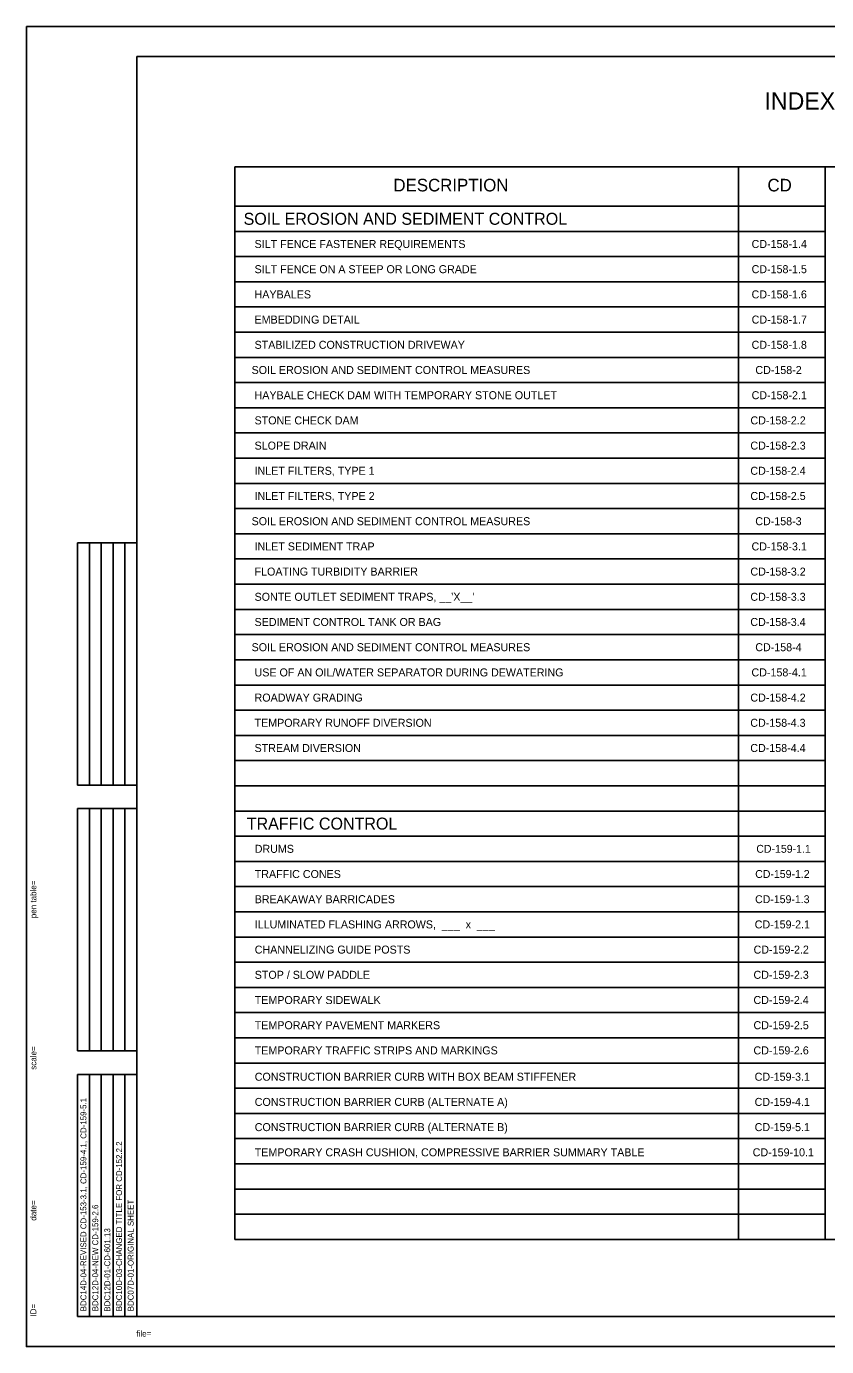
# Model space of a CAD drawing. Extents: x 503613 to 504661, y 498262 to 498922.
# Drawn here: x 503613 to 504013, y 498262 to 498922 of the extents above; entities that cross this region are included whole.
import ezdxf

# ---------------------------------------------------------------- set-up
doc = ezdxf.new("R2010")
doc.units = 0
for name, color, linetype in [('1', 7, 'Continuous'), ('39', 7, 'Continuous'), ('41', 7, 'Continuous')]:
    doc.layers.add(name, color=color, linetype=linetype)

msp = doc.modelspace()

# ---------------------------------------------------------------- linework, layer by layer
at = {"layer": '1'}
for p, q in [((504661.22, 498922.31), (503613.04, 498922.31)), ((504658.22, 498907.31), (503668.22, 498907.31)), ((503668.22, 498907.31), (503668.22, 498277.31)), ((503717.27, 498852.12), (504603.1, 498852.12)), ((503717.27, 498315.9), (503717.27, 498852.12)), ((503717.27, 498832.43), (503717.27, 498852.12)), ((503969.24, 498315.9), (503969.24, 498852.12)), ((503969.24, 498832.43), (503969.24, 498852.12)), ((504012.55, 498315.9), (504012.55, 498852.12)), ((504012.55, 498832.43), (504012.55, 498852.12)), ((503717.27, 498832.43), (504012.55, 498832.43)), ((503717.27, 498819.83), (504012.55, 498819.83)), ((503717.27, 498807.24), (504012.55, 498807.24)), ((503717.27, 498794.64), (504012.55, 498794.64)), ((503717.27, 498782.04), (504012.55, 498782.04)), ((503717.27, 498769.44), (504012.55, 498769.44)), ((503717.27, 498756.84), (504012.55, 498756.84)), ((503717.27, 498744.24), (504012.55, 498744.24)), ((503717.27, 498731.65), (504012.55, 498731.65)), ((503717.27, 498719.05), (504012.55, 498719.05)), ((503717.27, 498706.45), (504012.55, 498706.45)), ((503717.27, 498693.85), (504012.55, 498693.85)), ((503717.27, 498681.25), (504012.55, 498681.25)), ((503638.69, 498664.13), (503668.22, 498664.13)), ((503638.69, 498543.06), (503638.69, 498664.13)), ((503644.59, 498543.06), (503644.59, 498664.13)), ((503650.5, 498543.06), (503650.5, 498664.13)), ((503656.41, 498543.06), (503656.41, 498664.13)), ((503662.31, 498543.06), (503662.31, 498664.13)), ((503717.27, 498668.65), (504012.55, 498668.65)), ((503717.27, 498656.06), (504012.55, 498656.06)), ((503717.27, 498643.46), (504012.55, 498643.46)), ((503717.27, 498630.86), (504012.55, 498630.86)), ((503717.27, 498618.26), (504012.55, 498618.26)), ((503717.27, 498605.66), (504012.55, 498605.66)), ((503717.27, 498593.06), (504012.55, 498593.06)), ((503717.27, 498580.46), (504012.55, 498580.46)), ((503717.27, 498567.87), (504012.55, 498567.87)), ((503717.27, 498555.27), (504012.55, 498555.27)), ((503668.22, 498543.06), (503638.69, 498543.06)), ((503717.27, 498542.67), (504012.55, 498542.67)), ((503638.69, 498531.25), (503668.22, 498531.25)), ((503638.69, 498410.19), (503638.69, 498531.25)), ((503644.59, 498410.19), (503644.59, 498531.25)), ((503650.5, 498410.19), (503650.5, 498531.25)), ((503656.41, 498410.19), (503656.41, 498531.25)), ((503662.31, 498410.19), (503662.31, 498531.25)), ((503717.27, 498530.07), (504012.55, 498530.07)), ((503717.27, 498517.47), (504012.55, 498517.47)), ((503717.27, 498504.87), (504012.55, 498504.87)), ((503717.27, 498492.28), (504012.55, 498492.28)), ((503717.27, 498479.68), (504012.55, 498479.68)), ((503717.27, 498467.08), (504012.55, 498467.08)), ((503717.27, 498454.48), (504012.55, 498454.48)), ((503717.27, 498441.88), (504012.55, 498441.88)), ((503717.27, 498429.28), (504012.55, 498429.28)), ((503717.27, 498416.68), (504012.55, 498416.68)), ((503668.22, 498410.19), (503638.69, 498410.19)), ((503717.27, 498404.09), (504012.55, 498404.09)), ((503638.69, 498277.31), (503638.69, 498398.38)), ((503638.69, 498398.38), (503668.22, 498398.38)), ((503644.59, 498277.31), (503644.59, 498398.38)), ((503650.5, 498277.31), (503650.5, 498398.38)), ((503656.41, 498277.31), (503656.41, 498398.38)), ((503662.31, 498277.31), (503662.31, 498398.38)), ((503717.27, 498391.49), (504012.55, 498391.49)), ((503717.27, 498378.89), (504012.55, 498378.89)), ((503717.27, 498366.29), (504012.55, 498366.29)), ((503717.27, 498353.69), (504012.55, 498353.69)), ((503717.27, 498341.09), (504012.55, 498341.09)), ((503717.27, 498328.5), (504012.55, 498328.5)), ((503717.27, 498315.9), (504603.1, 498315.9)), ((503717.27, 498315.9), (504012.55, 498315.9)), ((503668.22, 498277.31), (503638.69, 498277.31)), ((503668.22, 498277.31), (504658.22, 498277.31)), ((504661.22, 498262.31), (503613.04, 498262.31))]:
    msp.add_line(p, q, dxfattribs=at)
at = {"layer": '41'}
msp.add_lwpolyline([(503613.04, 498922.31), (504661.22, 498922.31), (504661.22, 498262.31), (503613.04, 498262.31)], close=True, dxfattribs=at)

# ---------------------------------------------------------------- texts
at = {"layer": '1'}
for s, height, p in [('DESCRIPTION', 6.2992, (503796.64, 498839.82)), ('CD', 6.299, (503983.75, 498839.82))]:
    msp.add_text(s, height=height, dxfattribs=at).set_placement(p)
for s, height, rotation, p in [('...................pentable..................', 0.0432, 90, (503618.04, 498500.38)), ('pen table=', 3, 90, (503618.04, 498476.47)), ('scale=', 3, 90, (503618.04, 498400.71)), ('......scale......', 0.0432, 90, (503618.04, 498415.38)), ('date=', 3, 90, (503618.04, 498325.25)), ('.......time......', 0.0432, 90, (503618.04, 498338.38)), ('ID=', 3, 90, (503618.04, 498277.34)), ('............who............', 0.0432, 90, (503618.04, 498285.31)), ('file=', 3, 360, (503668.05, 498267.31)), ('...................bob..................', 0.0432, 360, (503678.04, 498267.31))]:
    msp.add_text(s, height=height, rotation=rotation, dxfattribs=at).set_placement(p)
at = {"layer": '39'}
for s, height, p in [('INDEX FOR STANDARD ROADWAY CONSTRUCTION DETAILS', 8.6614, (503982.24, 498880.71)), ('SOIL EROSION AND SEDIMENT CONTROL ', 6, (503721.7, 498823.13)), (' SILT FENCE FASTENER REQUIREMENTS', 4, (503725.7, 498811.53)), ('CD-158-1.4', 4, (503975.81, 498811.53)), (' SILT FENCE ON A STEEP OR LONG GRADE', 4, (503725.7, 498798.94)), ('CD-158-1.5', 4, (503975.81, 498798.94)), (' HAYBALES', 4, (503725.7, 498786.34)), ('CD-158-1.6', 4, (503975.81, 498786.34)), (' EMBEDDING DETAIL', 4, (503725.7, 498773.74)), ('CD-158-1.7', 4, (503975.83, 498773.74)), (' STABILIZED CONSTRUCTION DRIVEWAY', 4, (503725.7, 498761.14)), ('CD-158-1.8', 4, (503975.81, 498761.14)), ('SOIL EROSION AND SEDIMENT CONTROL MEASURES', 4, (503725.7, 498748.54)), ('CD-158-2', 4, (503977.69, 498748.54)), (' HAYBALE CHECK DAM WITH TEMPORARY STONE OUTLET', 4, (503725.7, 498735.94)), ('CD-158-2.1', 4, (503975.81, 498735.94)), (' STONE CHECK DAM', 4, (503725.7, 498723.35)), ('CD-158-2.2', 4, (503975.24, 498723.35)), (' SLOPE DRAIN', 4, (503725.7, 498710.75)), ('CD-158-2.3', 4, (503975.21, 498710.75)), (' INLET FILTERS, TYPE 1', 4, (503725.7, 498698.15)), ('CD-158-2.4', 4, (503975.2, 498698.15)), (' INLET FILTERS, TYPE 2', 4, (503725.7, 498685.55)), ('CD-158-2.5', 4, (503975.21, 498685.55)), ('SOIL EROSION AND SEDIMENT CONTROL MEASURES', 4, (503725.7, 498672.95)), ('CD-158-3', 4, (503977.65, 498672.95)), (' INLET SEDIMENT TRAP', 4, (503725.7, 498660.35)), ('CD-158-3.1', 4, (503975.79, 498660.35)), (' FLOATING TURBIDITY BARRIER', 4, (503725.7, 498647.76)), ('CD-158-3.2', 4, (503975.22, 498647.76)), (" SONTE OUTLET SEDIMENT TRAPS, __'X__'", 4, (503725.7, 498635.16)), ('CD-158-3.3', 4, (503975.19, 498635.16)), (' SEDIMENT CONTROL TANK OR BAG', 4, (503725.7, 498622.56)), ('CD-158-3.4', 4, (503975.18, 498622.56)), ('SOIL EROSION AND SEDIMENT CONTROL MEASURES', 4, (503725.7, 498609.96)), ('CD-158-4', 4, (503977.65, 498609.96)), (' USE OF AN OIL/WATER SEPARATOR DURING DEWATERING', 4, (503725.7, 498597.36)), ('CD-158-4.1', 4, (503975.76, 498597.36)), (' ROADWAY GRADING', 4, (503725.7, 498584.76)), ('CD-158-4.2', 4, (503975.2, 498584.76)), (' TEMPORARY RUNOFF DIVERSION', 4, (503725.7, 498572.16)), ('CD-158-4.3', 4, (503975.16, 498572.16)), (' STREAM DIVERSION', 4, (503725.7, 498559.57)), ('CD-158-4.4', 4, (503975.16, 498559.57)), ('TRAFFIC CONTROL', 6, (503723.27, 498520.77)), ('DRUMS', 4, (503727.27, 498509.17)), ('CD-159-1.1', 3.937, (503978.17, 498509.2)), ('TRAFFIC CONES', 4, (503727.27, 498496.57)), ('CD-159-1.2', 3.937, (503977.62, 498496.61)), ('BREAKAWAY BARRICADES', 4, (503727.27, 498483.98)), ('CD-159-1.3', 3.937, (503977.58, 498484.01)), ('ILLUMINATED FLASHING ARROWS,  ___  x  ___ ', 4, (503727.27, 498471.38)), ('CD-159-2.1', 4, (503977.36, 498471.38)), ('CHANNELIZING GUIDE POSTS', 4, (503727.27, 498458.78)), ('CD-159-2.2', 4, (503976.8, 498458.78)), ('STOP / SLOW PADDLE', 4, (503727.27, 498446.18)), ('CD-159-2.3', 4, (503976.76, 498446.18)), ('TEMPORARY SIDEWALK', 4, (503727.27, 498433.58)), ('CD-159-2.4', 4, (503976.75, 498433.58)), ('TEMPORARY PAVEMENT MARKERS', 4, (503727.27, 498420.98)), ('CD-159-2.5', 4, (503976.76, 498420.98)), ('TEMPORARY TRAFFIC STRIPS AND MARKINGS', 4, (503727.27, 498408.39)), ('CD-159-2.6', 4, (503976.76, 498408.39)), ('CONSTRUCTION BARRIER CURB WITH BOX BEAM STIFFENER', 4, (503727.27, 498395.23)), ('CD-159-3.1', 4, (503977.34, 498395.23)), ('CONSTRUCTION BARRIER CURB (ALTERNATE A)', 4, (503727.27, 498382.63)), ('CD-159-4.1', 4, (503977.32, 498382.63)), ('CONSTRUCTION BARRIER CURB (ALTERNATE B)', 4, (503727.27, 498370.04)), ('CD-159-5.1', 4, (503977.34, 498370.04)), ('TEMPORARY CRASH CUSHION, COMPRESSIVE BARRIER SUMMARY TABLE', 4, (503727.27, 498357.44)), ('CD-159-10.1', 4, (503976.36, 498357.44))]:
    msp.add_text(s, height=height, dxfattribs=at).set_placement(p)
for s, p in [('BDC14D-04-REVISED CD-153-3.1, CD-159-4.1, CD-159-5.1', (503643.06, 498279.98)), ('BDC10D-03-CHANGED TITLE FOR CD-152.2.2', (503660.89, 498279.98)), ('BDC12D-04-NEW CD-159-2.6', (503648.97, 498279.98)), ('BDC07D-01-ORIGINAL SHEET', (503666.69, 498279.98)), ('BDC12D-01-CD-601.13', (503654.98, 498279.79))]:
    msp.add_text(s, height=2.9528, rotation=90, dxfattribs=at).set_placement(p)

doc.saveas('drawing.dxf')
